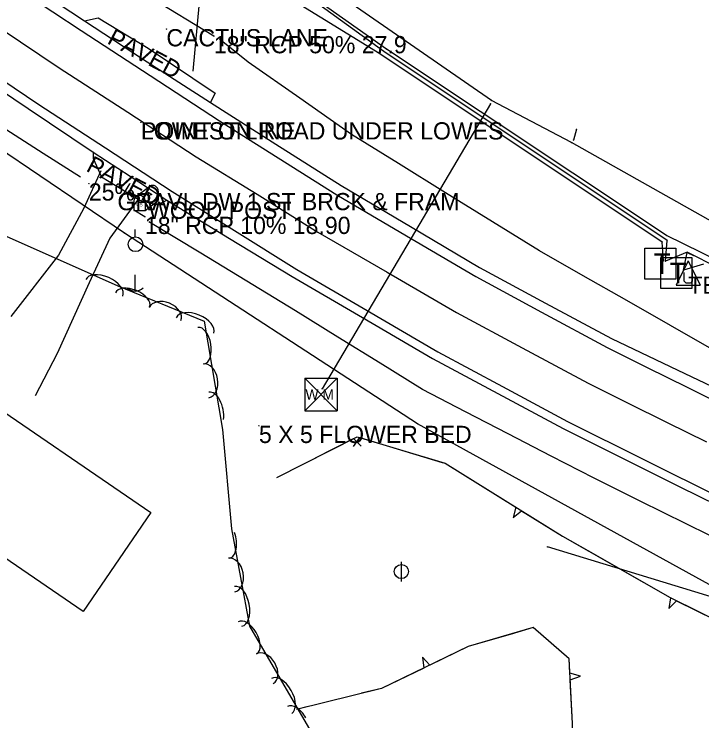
# Model space of a CAD drawing. Extents: x 954793 to 988390, y 1867850 to 1924428.
# Drawn here: x 962638.7 to 962838.1, y 1901065.8 to 1901270.8 of the extents above; entities that cross this region are included whole.
import ezdxf

# ---------------------------------------------------------------- set-up
doc = ezdxf.new("R2010")
doc.units = 0
for name, color, linetype in [('S_BUILDING', 7, 'Continuous'), ('S_DITCHLINE', 7, 'Continuous'), ('S_DRG_PT_SYM', 7, 'Continuous'), ('S_EDGE_BITUMINOUS', 7, 'Continuous'), ('S_EDGE_PAVEMENT', 7, 'Continuous'), ('S_ELECTRIC_UTILITIES_ANNOT', 7, 'Continuous'), ('S_FIBER_OPTIC_CABLE', 7, 'Continuous'), ('S_GRAVEL_ROAD', 7, 'Continuous'), ('S_MAILBOX', 7, 'Continuous'), ('S_MAILBOX_ANNOT', 7, 'Continuous'), ('S_MSC_PT_SYM', 7, 'Continuous'), ('S_PARKING_ANNOT', 7, 'Continuous'), ('S_PAVEMENT_CROWN', 7, 'Continuous'), ('S_SHOULDER', 7, 'Continuous'), ('S_SIDE_DRAIN', 7, 'Continuous'), ('S_SIDE_DRAIN_ANNOT', 7, 'Continuous'), ('S_SURVEY_TEXT_ANNOT', 7, 'Continuous'), ('S_TELEPHONE_UTILITIES', 7, 'Continuous'), ('S_TREE', 7, 'Continuous'), ('S_UNDERGROUND_CABLE', 7, 'Continuous'), ('S_UTILITY_POLE', 7, 'Continuous'), ('S_UTILITY_POLE_ANNOT', 7, 'Continuous'), ('S_UTL_PT_SYM', 7, 'Continuous'), ('S_WATER_UTILITIES', 7, 'Continuous')]:
    doc.layers.add(name, color=color, linetype=linetype)

msp = doc.modelspace()

# ---------------------------------------------------------------- linework, layer by layer
at = {"layer": 'S_BUILDING'}
msp.add_lwpolyline([(962658.64, 1901097.51), (962605.5, 1901133.89), (962625.14, 1901162.58), (962678.28, 1901126.2)], close=True, dxfattribs=at)
at = {"layer": 'S_DITCHLINE'}
for points in [[(962657.91, 1901223.48), (962647.08, 1901230.43), (962636.25, 1901237.38), (962625.42, 1901244.33), (962614.59, 1901251.28), (962599.87, 1901261.6), (962585.15, 1901271.93), (962570.43, 1901282.26), (962555.71, 1901292.58), (962536.86, 1901304.88), (962518, 1901317.17), (962499.15, 1901329.46), (962480.29, 1901341.76), (962468.04, 1901351.54), (962455.79, 1901361.33), (962443.54, 1901371.12), (962431.28, 1901380.91)], [(962862.29, 1901163.94), (962841.7, 1901173.28), (962829.02, 1901180.49), (962816.35, 1901187.7), (962803.68, 1901194.91), (962791.01, 1901202.11), (962777.36, 1901210.56), (962763.72, 1901219.01), (962750.08, 1901227.46), (962736.44, 1901235.91), (962721.47, 1901246.41), (962706.5, 1901256.92), (962698.25, 1901263.58)], [(962846.91, 1901116.34), (962833.55, 1901122.94), (962820.2, 1901129.54), (962806.84, 1901136.15), (962794.4, 1901142.59), (962781.95, 1901149.04), (962769.51, 1901155.48), (962757.06, 1901161.93), (962744.78, 1901169.52), (962732.49, 1901177.11), (962720.21, 1901184.71), (962707.92, 1901192.3), (962692.82, 1901201.43), (962677.73, 1901210.57)]]:
    msp.add_lwpolyline(points, dxfattribs=at)
at = {"layer": 'S_DRG_PT_SYM'}
for points in [[(962696.58, 1901264.46), (962696.58, 1901264.51), (962696.58, 1901264.46), (962696.53, 1901264.46), (962696.58, 1901264.46), (962696.58, 1901264.41), (962696.58, 1901264.46), (962696.63, 1901264.46)], [(962660.32, 1901221.73), (962660.32, 1901221.78), (962660.32, 1901221.73), (962660.27, 1901221.73), (962660.32, 1901221.73), (962660.32, 1901221.68), (962660.32, 1901221.73), (962660.37, 1901221.73)], [(962676.58, 1901212.03), (962676.58, 1901212.08), (962676.58, 1901212.03), (962676.53, 1901212.03), (962676.58, 1901212.03), (962676.58, 1901211.98), (962676.58, 1901212.03), (962676.63, 1901212.03)]]:
    msp.add_lwpolyline(points, dxfattribs=at)
at = {"layer": 'S_EDGE_BITUMINOUS'}
for points in [[(962659.08, 1901268.9), (962663.02, 1901269.79), (962677.52, 1901260.96), (962696.95, 1901247.89), (962695.55, 1901245.32)], [(962661.59, 1901230.85), (962661.56, 1901228.95), (962664, 1901223.62), (962675.11, 1901216.84), (962680.14, 1901215.5), (962682.92, 1901216.85)]]:
    msp.add_lwpolyline(points, dxfattribs=at)
at = {"layer": 'S_EDGE_PAVEMENT'}
for points in [[(962483.37, 1901356.26), (962485.16, 1901355), (962496.14, 1901347.26), (962507.11, 1901339.52), (962518.09, 1901331.78), (962529.07, 1901324.04), (962539.85, 1901316.63), (962550.63, 1901309.22), (962561.41, 1901301.8), (962572.2, 1901294.39), (962591, 1901281.55), (962609.8, 1901268.71), (962627.81, 1901256.65), (962645.82, 1901244.59), (962665.15, 1901231.99), (962684.48, 1901219.39), (962702.54, 1901208.06), (962720.6, 1901196.73), (962741.04, 1901184.8), (962761.48, 1901172.88), (962780.31, 1901162.76), (962799.13, 1901152.64), (962821.45, 1901141.54), (962843.77, 1901130.43)], [(962609.24, 1901298.92), (962625.27, 1901287.95), (962641.68, 1901277), (962658.08, 1901266.04), (962678.13, 1901252.97), (962698.18, 1901239.91), (962715.2, 1901229.14), (962732.21, 1901218.37), (962752.39, 1901206.52), (962772.57, 1901194.67), (962791.62, 1901184.39), (962810.66, 1901174.1), (962822.26, 1901168.34), (962833.85, 1901162.59), (962845.45, 1901156.83), (962857.05, 1901151.07), (962876.37, 1901142.21), (962895.7, 1901133.34), (962918.48, 1901123.51), (962934.07, 1901116.97)]]:
    msp.add_lwpolyline(points, dxfattribs=at)
at = {"layer": 'S_FIBER_OPTIC_CABLE'}
for p, q in [((962670.68, 1901207.24), (962400.06, 1901390.47)), ((962744.73, 1901259.35), (962678.47, 1901300.02)), ((962745.87, 1901260.01), (962700.96, 1901292.47)), ((962746.64, 1901260.63), (962701.02, 1901292.89)), ((962826.6, 1901204.71), (962744.73, 1901259.35)), ((962828.02, 1901205.11), (962745.87, 1901260.01)), ((962827.88, 1901206.64), (962746.64, 1901260.63)), ((962755.66, 1901151.99), (962670.68, 1901207.24)), ((962879.13, 1901181.13), (962827.88, 1901206.64)), ((962826.93, 1901199.21), (962826.6, 1901204.71)), ((962827.5, 1901199.17), (962828.02, 1901205.11)), ((962833.85, 1901201.78), (962827.5, 1901199.17)), ((962832.75, 1901196.57), (962833.87, 1901201.67)), ((962877.25, 1901179.65), (962833.85, 1901201.78)), ((962833.87, 1901201.67), (962835.62, 1901200.77)), ((962838.58, 1901198.3), (962832.75, 1901196.57)), ((962852.34, 1901098.57), (962755.66, 1901151.99)), ((962849.98, 1901098.91), (962793.37, 1901116.27))]:
    msp.add_line(p, q, dxfattribs=at)
at = {"layer": 'S_GRAVEL_ROAD'}
msp.add_lwpolyline([(962690.6, 1901254.26), (962692.41, 1901274.17)], dxfattribs=at)
at = {"layer": 'S_MAILBOX'}
for p, q in [((962673.88, 1901217.84), (962678.01, 1901220.95)), ((962677.49, 1901219.13), (962677.49, 1901216.42)), ((962680.44, 1901219.48), (962680.44, 1901216.76)), ((962673.32, 1901216.57), (962673.32, 1901213.86)), ((962676.65, 1901213.86), (962680.44, 1901216.76)), ((962676.65, 1901216.57), (962676.65, 1901213.86)), ((962673.32, 1901213.86), (962676.65, 1901213.86))]:
    msp.add_line(p, q, dxfattribs=at)
for points in [[(962677.49, 1901219.13), (962678.6, 1901218.47), (962677.49, 1901218.12)], [(962674.51, 1901217.69), (962674.73, 1901217.55), (962674.73, 1901217.16), (962675.03, 1901217.16), (962675.03, 1901217.52), (962674.84, 1901217.77), (962674.51, 1901217.71)]]:
    msp.add_lwpolyline(points, dxfattribs=at)
for centre, end in [((962678.78, 1901219.48), 117.5718), ((962674.98, 1901216.57), 180)]:
    msp.add_arc(centre, 1.66, 0, end, dxfattribs=at)
msp.add_ellipse((962677.49, 1901216.42), major_axis=(0.145, 0.132), ratio=0.564646, dxfattribs=at)
at = {"layer": 'S_MSC_PT_SYM'}
for points in [[(962682.82, 1901266.47), (962682.82, 1901266.52), (962682.82, 1901266.47), (962682.77, 1901266.47), (962682.82, 1901266.47), (962682.82, 1901266.42), (962682.82, 1901266.47), (962682.87, 1901266.47)], [(962675.42, 1901239.45), (962675.42, 1901239.5), (962675.42, 1901239.45), (962675.37, 1901239.45), (962675.42, 1901239.45), (962675.42, 1901239.4), (962675.42, 1901239.45), (962675.47, 1901239.45)], [(962668.6, 1901218.93), (962668.6, 1901218.98), (962668.6, 1901218.93), (962668.55, 1901218.93), (962668.6, 1901218.93), (962668.6, 1901218.88), (962668.6, 1901218.93), (962668.65, 1901218.93)], [(962709.65, 1901151.39), (962709.65, 1901151.44), (962709.65, 1901151.39), (962709.6, 1901151.39), (962709.65, 1901151.39), (962709.65, 1901151.34), (962709.65, 1901151.39), (962709.7, 1901151.39)]]:
    msp.add_lwpolyline(points, dxfattribs=at)
at = {"layer": 'S_PARKING_ANNOT'}
for p, q in [((962663.82, 1901225.31), (962658.84, 1901214.53)), ((962674.71, 1901217.28), (962666.37, 1901205.84)), ((962658.84, 1901214.53), (962651.52, 1901200.93)), ((962666.37, 1901205.84), (962660.45, 1901192.87)), ((962651.52, 1901200.93), (962637.7, 1901183.05)), ((962660.45, 1901192.87), (962651.16, 1901172.37)), ((962651.16, 1901172.37), (962644.79, 1901160.09))]:
    msp.add_line(p, q, dxfattribs=at)
at = {"layer": 'S_PAVEMENT_CROWN'}
msp.add_lwpolyline([(962634.89, 1901266.6), (962651.74, 1901255.28), (962671.6, 1901242.37), (962691.46, 1901229.46), (962709.09, 1901218.54), (962726.72, 1901207.61), (962746.84, 1901195.95), (962766.95, 1901184.3), (962786.02, 1901174.03), (962805.1, 1901163.76), (962816.56, 1901158.07), (962828.02, 1901152.38), (962839.48, 1901146.69)], dxfattribs=at)
msp.add_lwpolyline([(962634.89, 1901266.6), (962651.74, 1901255.28), (962671.6, 1901242.37), (962691.46, 1901229.46), (962709.09, 1901218.54), (962726.72, 1901207.61), (962746.84, 1901195.95), (962766.95, 1901184.3), (962786.02, 1901174.03), (962805.1, 1901163.76), (962816.56, 1901158.07), (962828.02, 1901152.38), (962839.48, 1901146.69)], dxfattribs=at)
at = {"layer": 'S_SHOULDER'}
for points in [[(962610.98, 1901301.16), (962626.83, 1901290.33), (962642.94, 1901279.61), (962659.04, 1901268.9), (962675.88, 1901257.83), (962695.58, 1901245.15), (962714.54, 1901233.11), (962733.5, 1901221.06), (962753.55, 1901209.19), (962773.6, 1901197.32), (962792.74, 1901187.01), (962811.88, 1901176.71), (962833.18, 1901166.54), (962854.49, 1901156.38)], [(962625.73, 1901254.86), (962642.76, 1901243.42), (962661.59, 1901230.81), (962672.26, 1901223.85), (962682.92, 1901216.88), (962701.11, 1901205.77), (962719.29, 1901194.67), (962739.63, 1901182.79), (962759.98, 1901170.91), (962778.93, 1901160.78), (962797.88, 1901150.65), (962809.09, 1901145.04), (962820.3, 1901139.43), (962831.51, 1901133.82), (962842.72, 1901128.22)]]:
    msp.add_lwpolyline(points, dxfattribs=at)
at = {"layer": 'S_SIDE_DRAIN'}
for p, q in [((962696.58, 1901264.46), (962677.54, 1901276.01)), ((962676.58, 1901212.03), (962673.32, 1901213.97))]:
    msp.add_line(p, q, dxfattribs=at)
at = {"layer": 'S_TELEPHONE_UTILITIES'}
for points in [[(962821.54, 1901193.9), (962821.54, 1901202.9), (962830.54, 1901202.9), (962830.54, 1901193.9)], [(962826.19, 1901191.22), (962826.19, 1901200.22), (962835.19, 1901200.22), (962835.19, 1901191.22)]]:
    msp.add_lwpolyline(points, close=True, dxfattribs=at)
at = {"layer": 'S_TREE'}
for p, q in [((962737.04, 1901145.4), (962738.88, 1901147.98)), ((962737.08, 1901147.68), (962739.28, 1901145.43)), ((962784.16, 1901127.8), (962783.38, 1901124.75)), ((962783.38, 1901124.75), (962785.83, 1901126.76)), ((962828.98, 1901101.51), (962828.5, 1901098.4)), ((962828.5, 1901098.4), (962830.74, 1901100.64)), ((962759.19, 1901081.95), (962757.04, 1901084.24)), ((962757.04, 1901084.24), (962757.42, 1901081.1)), ((962802.86, 1901078.75), (962799.81, 1901079.61)), ((962799.91, 1901077.65), (962802.86, 1901078.75))]:
    msp.add_line(p, q, dxfattribs=at)
for points in [[(962597.42, 1901063.1), (962590.85, 1901082.64), (962591.6, 1901098.53), (962579.33, 1901117.03), (962557.56, 1901129.94), (962536.38, 1901139.69), (962522.07, 1901148.37), (962519.58, 1901169.37), (962511.98, 1901195.49), (962510.06, 1901220.17), (962494.29, 1901244.22), (962492.64, 1901262.43), (962506.45, 1901276.67), (962538.71, 1901263.76), (962573.92, 1901246.47), (962592.4, 1901217.23), (962612.5, 1901203.52), (962636.31, 1901206.38), (962668.76, 1901191.98), (962693.8, 1901181.7), (962699.12, 1901150.31), (962701.71, 1901121.46), (962706.87, 1901093.24), (962724.66, 1901062.69)], [(962714.79, 1901136.34), (962738.12, 1901148.21), (962763.68, 1901140.52), (962797.72, 1901119.37), (962828.91, 1901101.54), (962853.59, 1901089.4), (962874.47, 1901090.72), (962899.4, 1901083.13), (962928.34, 1901072.45), (962964.69, 1901056.17), (962990.4, 1901046.21), (963022.32, 1901027.22), (963049.54, 1901018.24), (963078.3, 1901007.85), (963117.13, 1900998.98), (963146.33, 1900984.01), (963177.65, 1900928.77), (963178.53, 1900897.92), (963163.3, 1900878.27), (963143.63, 1900874.91)], [(962726.09, 1901142.08), (962737.08, 1901147.68)], [(962738.88, 1901147.98), (962762.82, 1901140.78)], [(962762.82, 1901140.78), (962763.68, 1901140.52), (962784.16, 1901127.8)], [(962785.83, 1901126.76), (962797.72, 1901119.37), (962807.27, 1901113.91)], [(962807.27, 1901113.91), (962828.91, 1901101.54), (962828.98, 1901101.51)], [(962830.74, 1901100.64), (962853.17, 1901089.6)], [(962843.62, 1900953.26), (962835.15, 1900927.27), (962819.83, 1900896.14), (962810.97, 1900889.42), (962794.63, 1900892.96), (962782.43, 1900913.82), (962785.84, 1900939.39), (962787.36, 1900974.35), (962800.77, 1901008.08), (962800.2, 1901037.73), (962800.59, 1901064.97), (962799.59, 1901083.78), (962789.19, 1901092.86), (962770.35, 1901087.31), (962745.16, 1901075.21), (962720.53, 1901069.09)], [(962799.81, 1901079.61), (962799.59, 1901083.78), (962789.19, 1901092.86), (962782.46, 1901090.88)], [(962782.46, 1901090.88), (962770.35, 1901087.31), (962759.19, 1901081.95)], [(962757.42, 1901081.1), (962745.16, 1901075.21), (962739.43, 1901073.78)], [(962800.41, 1901052.66), (962800.59, 1901064.97), (962799.91, 1901077.65)], [(962723.54, 1901069.84), (962720.53, 1901069.09)]]:
    msp.add_lwpolyline(points, dxfattribs=at)
for centre, major_axis, ratio, start_param, end_param in [((962664.78, 1901191.42), (-5.36, 2.38), 0.55008, 3.141593, 6.283185), ((962673, 1901187.94), (-4.95, 2.03), 0.540699, 3.141593, 6.283185), ((962682.43, 1901183.79), (-4.58, 1.88), 0.685311, 3.141593, 6.283185), ((962691.1, 1901180.51), (-5.43, 2.23), 0.55008, 3.141593, 6.283185), ((962692.85, 1901174.62), (-0.89, 5.27), 0.540699, 3.141593, 6.283185), ((962694.31, 1901164.42), (-0.83, 4.89), 0.685311, 3.141593, 6.283185), ((962696.12, 1901155.34), (-0.98, 5.79), 0.55008, 4.238754, 6.283185), ((962700.14, 1901118.25), (-0.96, 5.26), 0.540699, 3.141593, 5.033137), ((962701.73, 1901108.07), (-0.89, 4.87), 0.685311, 3.141593, 6.283185), ((962703.66, 1901099.01), (-1.06, 5.77), 0.55008, 3.141593, 6.283185), ((962706.35, 1901089.92), (-2.69, 4.62), 0.540699, 3.141593, 6.283185), ((962711.31, 1901080.88), (-2.49, 4.28), 0.685311, 3.141593, 6.283185), ((962716.19, 1901073.01), (-2.95, 5.07), 0.55008, 3.141593, 6.283185), ((962720.66, 1901065.35), (-2.69, 4.62), 0.540699, 4.678585, 6.283185)]:
    msp.add_ellipse(centre, major_axis=major_axis, ratio=ratio, start_param=start_param, end_param=end_param, dxfattribs=at)
at = {"layer": 'S_UNDERGROUND_CABLE'}
for p, q in [((962834.15, 1901199.23), (962830.63, 1901192.14)), ((962834.15, 1901199.23), (962837.64, 1901192.14)), ((962832.95, 1901193.38), (962832.95, 1901195.82)), ((962835.32, 1901195.82), (962835.32, 1901193.38)), ((962833.57, 1901192.72), (962832.95, 1901193.38)), ((962835.32, 1901193.38), (962834.77, 1901192.72)), ((962830.63, 1901192.14), (962837.64, 1901192.14)), ((962834.77, 1901192.72), (962833.57, 1901192.72))]:
    msp.add_line(p, q, dxfattribs=at)
at = {"layer": 'S_UTILITY_POLE'}
for p, q in [((962673.72, 1901206.2), (962673.72, 1901208.31)), ((962673.67, 1901195.2), (962673.67, 1901190.47)), ((962750.95, 1901106.17), (962750.95, 1901111.96))]:
    msp.add_line(p, q, dxfattribs=at)
for centre, radius in [((962673.84, 1901204.06), 2.13), ((962750.95, 1901109.1), 2.05)]:
    msp.add_circle(centre, radius, dxfattribs=at)
msp.add_arc((962673.73, 1901193.9), 3.41, 226.3972, 313.6028, dxfattribs=at)
at = {"layer": 'S_UTL_PT_SYM'}
for points in [[(962744.73, 1901259.35), (962744.73, 1901259.4), (962744.73, 1901259.35), (962744.68, 1901259.35), (962744.73, 1901259.35), (962744.73, 1901259.3), (962744.73, 1901259.35), (962744.78, 1901259.35)], [(962745.87, 1901260.01), (962745.87, 1901260.06), (962745.87, 1901260.01), (962745.82, 1901260.01), (962745.87, 1901260.01), (962745.87, 1901259.96), (962745.87, 1901260.01), (962745.92, 1901260.01)], [(962746.64, 1901260.63), (962746.64, 1901260.68), (962746.64, 1901260.63), (962746.59, 1901260.63), (962746.64, 1901260.63), (962746.64, 1901260.58), (962746.64, 1901260.63), (962746.69, 1901260.63)], [(962776.77, 1901244.81), (962776.77, 1901244.86), (962776.77, 1901244.81), (962776.72, 1901244.81), (962776.77, 1901244.81), (962776.77, 1901244.76), (962776.77, 1901244.81), (962776.82, 1901244.81)], [(962777.09, 1901245.73), (962777.09, 1901245.78), (962777.09, 1901245.73), (962777.04, 1901245.73), (962777.09, 1901245.73), (962777.09, 1901245.68), (962777.09, 1901245.73), (962777.14, 1901245.73)], [(962675.42, 1901239.45), (962675.42, 1901239.5), (962675.42, 1901239.45), (962675.37, 1901239.45), (962675.42, 1901239.45), (962675.42, 1901239.4), (962675.42, 1901239.45), (962675.47, 1901239.45)], [(962801.78, 1901237.44), (962801.78, 1901237.49), (962801.78, 1901237.44), (962801.73, 1901237.44), (962801.78, 1901237.44), (962801.78, 1901237.39), (962801.78, 1901237.44), (962801.83, 1901237.44)], [(962800.83, 1901234.28), (962800.83, 1901234.33), (962800.83, 1901234.28), (962800.78, 1901234.28), (962800.83, 1901234.28), (962800.83, 1901234.23), (962800.83, 1901234.28), (962800.88, 1901234.28)], [(962800.28, 1901233.55), (962800.28, 1901233.6), (962800.28, 1901233.55), (962800.23, 1901233.55), (962800.28, 1901233.55), (962800.28, 1901233.5), (962800.28, 1901233.55), (962800.33, 1901233.55)], [(962670.68, 1901207.24), (962670.68, 1901207.29), (962670.68, 1901207.24), (962670.63, 1901207.24), (962670.68, 1901207.24), (962670.68, 1901207.19), (962670.68, 1901207.24), (962670.73, 1901207.24)], [(962827.88, 1901206.64), (962827.88, 1901206.69), (962827.88, 1901206.64), (962827.83, 1901206.64), (962827.88, 1901206.64), (962827.88, 1901206.59), (962827.88, 1901206.64), (962827.93, 1901206.64)], [(962826.6, 1901204.71), (962826.6, 1901204.76), (962826.6, 1901204.71), (962826.55, 1901204.71), (962826.6, 1901204.71), (962826.6, 1901204.66), (962826.6, 1901204.71), (962826.65, 1901204.71)], [(962828.02, 1901205.11), (962828.02, 1901205.16), (962828.02, 1901205.11), (962827.97, 1901205.11), (962828.02, 1901205.11), (962828.02, 1901205.06), (962828.02, 1901205.11), (962828.07, 1901205.11)], [(962833.85, 1901201.78), (962833.85, 1901201.83), (962833.85, 1901201.78), (962833.8, 1901201.78), (962833.85, 1901201.78), (962833.85, 1901201.73), (962833.85, 1901201.78), (962833.9, 1901201.78)], [(962833.87, 1901201.67), (962833.87, 1901201.72), (962833.87, 1901201.67), (962833.82, 1901201.67), (962833.87, 1901201.67), (962833.87, 1901201.62), (962833.87, 1901201.67), (962833.92, 1901201.67)], [(962835.62, 1901200.77), (962835.62, 1901200.82), (962835.62, 1901200.77), (962835.57, 1901200.77), (962835.62, 1901200.77), (962835.62, 1901200.72), (962835.62, 1901200.77), (962835.67, 1901200.77)], [(962826.93, 1901199.21), (962826.93, 1901199.26), (962826.93, 1901199.21), (962826.88, 1901199.21), (962826.93, 1901199.21), (962826.93, 1901199.16), (962826.93, 1901199.21), (962826.98, 1901199.21)], [(962827.5, 1901199.17), (962827.5, 1901199.22), (962827.5, 1901199.17), (962827.45, 1901199.17), (962827.5, 1901199.17), (962827.5, 1901199.12), (962827.5, 1901199.17), (962827.55, 1901199.17)], [(962832.75, 1901196.57), (962832.75, 1901196.62), (962832.75, 1901196.57), (962832.7, 1901196.57), (962832.75, 1901196.57), (962832.75, 1901196.52), (962832.75, 1901196.57), (962832.8, 1901196.57)], [(962727.94, 1901162.13), (962727.94, 1901162.18), (962727.94, 1901162.13), (962727.89, 1901162.13), (962727.94, 1901162.13), (962727.94, 1901162.08), (962727.94, 1901162.13), (962727.99, 1901162.13)], [(962755.66, 1901151.99), (962755.66, 1901152.04), (962755.66, 1901151.99), (962755.61, 1901151.99), (962755.66, 1901151.99), (962755.66, 1901151.94), (962755.66, 1901151.99), (962755.71, 1901151.99)], [(962793.37, 1901116.27), (962793.37, 1901116.32), (962793.37, 1901116.27), (962793.32, 1901116.27), (962793.37, 1901116.27), (962793.37, 1901116.22), (962793.37, 1901116.27), (962793.42, 1901116.27)]]:
    msp.add_lwpolyline(points, dxfattribs=at)
at = {"layer": 'S_WATER_UTILITIES'}
for p, q in [((962777.09, 1901245.73), (962725.52, 1901281.52)), ((962776.77, 1901244.81), (962727.94, 1901162.13)), ((962800.28, 1901233.55), (962777.09, 1901245.73)), ((962801.78, 1901237.44), (962800.83, 1901234.28)), ((962871.35, 1901193.5), (962800.28, 1901233.55)), ((962722.95, 1901165.2), (962732.29, 1901165.2)), ((962722.95, 1901165.2), (962722.95, 1901155.7)), ((962722.95, 1901165.2), (962732.29, 1901155.7)), ((962732.29, 1901165.2), (962722.95, 1901155.7)), ((962732.29, 1901165.2), (962732.29, 1901155.7)), ((962722.95, 1901155.7), (962732.29, 1901155.7))]:
    msp.add_line(p, q, dxfattribs=at)

# ---------------------------------------------------------------- texts
at = {"layer": 'S_ELECTRIC_UTILITIES_ANNOT'}
msp.add_text('LOWEST LINE', height=5, dxfattribs=at).set_placement((962675.42, 1901234.45))
at = {"layer": 'S_MAILBOX'}
msp.add_text('US', height=0.96, rotation=360, dxfattribs=at).set_placement((962674.09, 1901215.05))
at = {"layer": 'S_MAILBOX_ANNOT'}
msp.add_text('WOOD POST', height=5, dxfattribs=at).set_placement((962677.49, 1901211.42))
at = {"layer": 'S_PARKING_ANNOT'}
for rotation, p in [(332.0389, (962665.35, 1901262.46)), (332.4803, (962659.26, 1901225.46))]:
    msp.add_text('PAVED', height=5, rotation=rotation, dxfattribs=at).set_placement(p)
at = {"layer": 'S_SIDE_DRAIN_ANNOT'}
for s, p in [('18" RCP 50% 27.9', (962696.58, 1901259.46)), ('25%', (962660.32, 1901216.73)), ('18" RCP 10% 18.90', (962676.58, 1901207.03))]:
    msp.add_text(s, height=5, dxfattribs=at).set_placement(p)
at = {"layer": 'S_SURVEY_TEXT_ANNOT'}
for s, p in [('CACTUS LANE', (962682.82, 1901261.47)), ('POINT ON ROAD UNDER LOWES', (962675.42, 1901234.45)), ('GRAVL DW 1 ST BRCK & FRAM', (962668.6, 1901213.93)), ('5 X 5 FLOWER BED', (962709.65, 1901146.39))]:
    msp.add_text(s, height=5, dxfattribs=at).set_placement(p)
at = {"layer": 'S_TELEPHONE_UTILITIES'}
for p in [(962824.1, 1901195.4), (962828.76, 1901192.72)]:
    msp.add_text('T', height=6, rotation=360, dxfattribs=at).set_placement(p)
at = {"layer": 'S_UTILITY_POLE_ANNOT'}
msp.add_text('TELE CENT AR COOP', height=5, dxfattribs=at).set_placement((962834.15, 1901189.69))
at = {"layer": 'S_WATER_UTILITIES'}
msp.add_text('W M', height=3, rotation=360, dxfattribs=at).set_placement((962723.15, 1901158.96))

doc.saveas('drawing.dxf')
